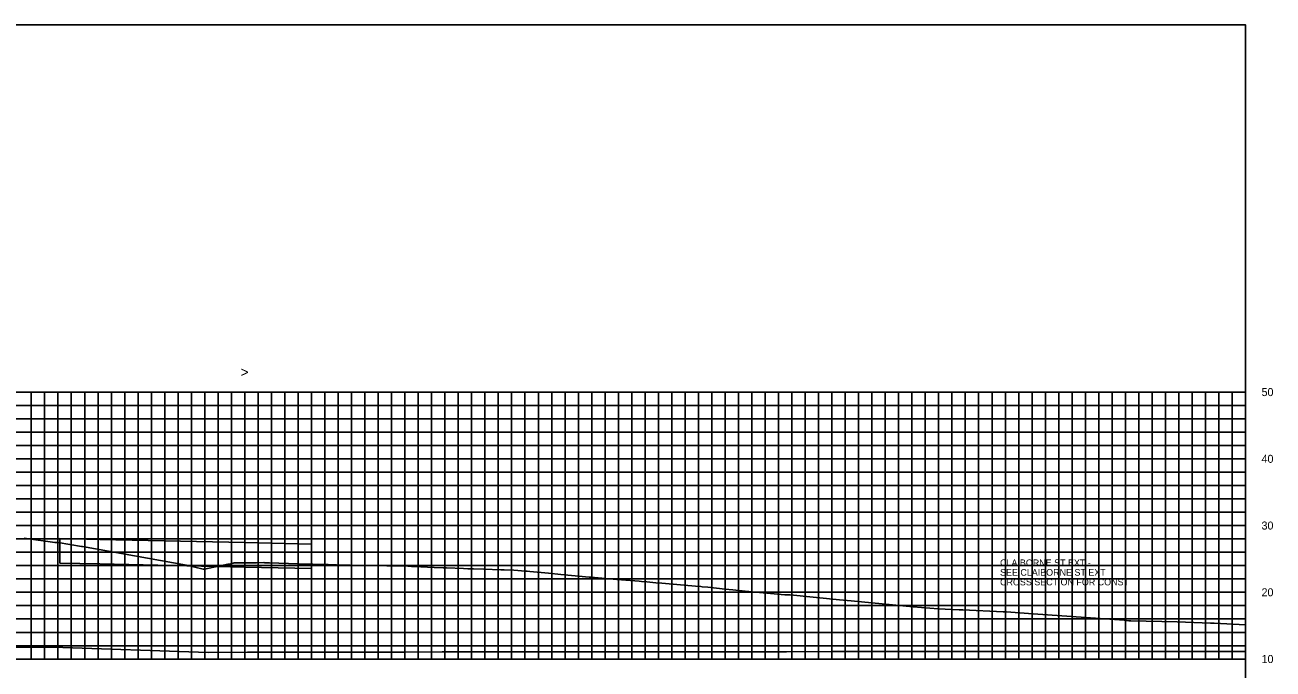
# Model space of a CAD drawing. Extents: x 1797305 to 1804485, y 245831 to 250849.
# Drawn here: x 1802938.1 to 1803125.1, y 250172.9 to 250269.4 of the extents above; entities that cross this region are included whole.
import ezdxf

# ---------------------------------------------------------------- set-up
doc = ezdxf.new("R2010")
doc.units = 0
for name, color, linetype in [('29', 7, 'Continuous'), ('60', 7, 'Continuous'), ('CL-CNST', 7, 'Continuous'), ('Level 31', 7, 'Continuous'), ('LIMT-CSLINE', 7, 'Continuous'), ('M-ROADS', 7, 'Continuous'), ('SURVEY - DRAINAGE - Area Shapes', 7, 'Continuous')]:
    doc.layers.add(name, color=color, linetype=linetype)

msp = doc.modelspace()

# ---------------------------------------------------------------- linework, layer by layer
msp.add_lwpolyline([(1802821, 250079.43), (1803121, 250079.43), (1803121, 250269.43), (1802821, 250269.43)], close=True)
at = {"layer": '29'}
for p, q in [((1802821, 250214.43), (1803121, 250214.43)), ((1802939, 250174.43), (1802939, 250214.43)), ((1802941, 250174.43), (1802941, 250214.43)), ((1802943, 250174.43), (1802943, 250214.43)), ((1802945, 250174.43), (1802945, 250214.43)), ((1802947, 250174.43), (1802947, 250214.43)), ((1802949, 250174.43), (1802949, 250214.43)), ((1802951, 250174.43), (1802951, 250214.43)), ((1802953, 250174.43), (1802953, 250214.43)), ((1802955, 250174.43), (1802955, 250214.43)), ((1802957, 250174.43), (1802957, 250214.43)), ((1802959, 250174.43), (1802959, 250214.43)), ((1802961, 250174.43), (1802961, 250214.43)), ((1802963, 250174.43), (1802963, 250214.43)), ((1802965, 250174.43), (1802965, 250214.43)), ((1802967, 250174.43), (1802967, 250214.43)), ((1802969, 250174.43), (1802969, 250214.43)), ((1802971, 250174.43), (1802971, 250214.43)), ((1802973, 250174.43), (1802973, 250214.43)), ((1802975, 250174.43), (1802975, 250214.43)), ((1802977, 250174.43), (1802977, 250214.43)), ((1802979, 250174.43), (1802979, 250214.43)), ((1802981, 250174.43), (1802981, 250214.43)), ((1802983, 250174.43), (1802983, 250214.43)), ((1802985, 250174.43), (1802985, 250214.43)), ((1802987, 250174.43), (1802987, 250214.43)), ((1802989, 250174.43), (1802989, 250214.43)), ((1802991, 250174.43), (1802991, 250214.43)), ((1802993, 250174.43), (1802993, 250214.43)), ((1802995, 250174.43), (1802995, 250214.43)), ((1802997, 250174.43), (1802997, 250214.43)), ((1802999, 250174.43), (1802999, 250214.43)), ((1803001, 250174.43), (1803001, 250214.43)), ((1803003, 250174.43), (1803003, 250214.43)), ((1803005, 250174.43), (1803005, 250214.43)), ((1803007, 250174.43), (1803007, 250214.43)), ((1803009, 250174.43), (1803009, 250214.43)), ((1803011, 250174.43), (1803011, 250214.43)), ((1803013, 250174.43), (1803013, 250214.43)), ((1803015, 250174.43), (1803015, 250214.43)), ((1803017, 250174.43), (1803017, 250214.43)), ((1803019, 250174.43), (1803019, 250214.43)), ((1803021, 250174.43), (1803021, 250214.43)), ((1803023, 250174.43), (1803023, 250214.43)), ((1803025, 250174.43), (1803025, 250214.43)), ((1803027, 250174.43), (1803027, 250214.43)), ((1803029, 250174.43), (1803029, 250214.43)), ((1803031, 250174.43), (1803031, 250214.43)), ((1803033, 250174.43), (1803033, 250214.43)), ((1803035, 250174.43), (1803035, 250214.43)), ((1803037, 250174.43), (1803037, 250214.43)), ((1803039, 250174.43), (1803039, 250214.43)), ((1803041, 250174.43), (1803041, 250214.43)), ((1803043, 250174.43), (1803043, 250214.43)), ((1803045, 250174.43), (1803045, 250214.43)), ((1803047, 250174.43), (1803047, 250214.43)), ((1803049, 250174.43), (1803049, 250214.43)), ((1803051, 250174.43), (1803051, 250214.43)), ((1803053, 250174.43), (1803053, 250214.43)), ((1803055, 250174.43), (1803055, 250214.43)), ((1803057, 250174.43), (1803057, 250214.43)), ((1803059, 250174.43), (1803059, 250214.43)), ((1803061, 250174.43), (1803061, 250214.43)), ((1803063, 250174.43), (1803063, 250214.43)), ((1803065, 250174.43), (1803065, 250214.43)), ((1803067, 250174.43), (1803067, 250214.43)), ((1803069, 250174.43), (1803069, 250214.43)), ((1803071, 250174.43), (1803071, 250214.43)), ((1803073, 250174.43), (1803073, 250214.43)), ((1803075, 250174.43), (1803075, 250214.43)), ((1803077, 250174.43), (1803077, 250214.43)), ((1803079, 250174.43), (1803079, 250214.43)), ((1803081, 250174.43), (1803081, 250214.43)), ((1803083, 250174.43), (1803083, 250214.43)), ((1803085, 250174.43), (1803085, 250214.43)), ((1803087, 250174.43), (1803087, 250214.43)), ((1803089, 250174.43), (1803089, 250214.43)), ((1803091, 250174.43), (1803091, 250214.43)), ((1803093, 250174.43), (1803093, 250214.43)), ((1803095, 250174.43), (1803095, 250214.43)), ((1803097, 250174.43), (1803097, 250214.43)), ((1803099, 250174.43), (1803099, 250214.43)), ((1803101, 250174.43), (1803101, 250214.43)), ((1803103, 250174.43), (1803103, 250214.43)), ((1803105, 250174.43), (1803105, 250214.43)), ((1803107, 250174.43), (1803107, 250214.43)), ((1803109, 250174.43), (1803109, 250214.43)), ((1803111, 250174.43), (1803111, 250214.43)), ((1803113, 250174.43), (1803113, 250214.43)), ((1803115, 250174.43), (1803115, 250214.43)), ((1803117, 250174.43), (1803117, 250214.43)), ((1803119, 250174.43), (1803119, 250214.43)), ((1803121, 250174.43), (1803121, 250214.43)), ((1802821, 250212.43), (1803121, 250212.43)), ((1802821, 250210.43), (1803121, 250210.43)), ((1802821, 250208.43), (1803121, 250208.43)), ((1802821, 250206.43), (1803121, 250206.43)), ((1802821, 250204.43), (1803121, 250204.43)), ((1802821, 250202.43), (1803121, 250202.43)), ((1802821, 250200.43), (1803121, 250200.43)), ((1802821, 250198.43), (1803121, 250198.43)), ((1802821, 250196.43), (1803121, 250196.43)), ((1802821, 250194.43), (1803121, 250194.43)), ((1802821, 250192.43), (1803121, 250192.43)), ((1802821, 250190.43), (1803121, 250190.43)), ((1802821, 250188.43), (1803121, 250188.43)), ((1802821, 250186.43), (1803121, 250186.43)), ((1802821, 250184.43), (1803121, 250184.43)), ((1802821, 250182.43), (1803121, 250182.43)), ((1802821, 250180.43), (1803121, 250180.43)), ((1802821, 250178.43), (1803121, 250178.43)), ((1802821, 250176.43), (1803121, 250176.43)), ((1802821, 250174.43), (1803121, 250174.43))]:
    msp.add_line(p, q, dxfattribs=at)
at = {"layer": 'CL-CNST'}
for points in [[(1802943.29, 250192.49), (1802949.29, 250192.36), (1802971, 250191.88), (1802981, 250191.66)], [(1802821, 250176.09), (1802825.63, 250176.01), (1802836.51, 250176.07), (1802854.79, 250176.25), (1802871.5, 250176.14), (1802883.94, 250176.21), (1802900.36, 250176.47), (1802913.1, 250176.53), (1802929.15, 250176.11), (1802942.26, 250176.19), (1802965.49, 250175.42), (1802971.42, 250175.46), (1802994.91, 250175.46), (1803000.58, 250175.49), (1803023.88, 250175.49), (1803029.74, 250175.52), (1803052.2, 250175.53), (1803058.9, 250175.54), (1803066.05, 250175.54), (1803088.05, 250175.56), (1803096.69, 250175.54), (1803117.21, 250175.56), (1803121, 250175.54)]]:
    msp.add_lwpolyline(points, dxfattribs=at)
at = {"layer": 'Level 31'}
for p, q in [((1803121, 250174.43), (1803121, 250214.43)), ((1803121.06, 250214.43), (1803121, 250214.43)), ((1803121.06, 250204.43), (1803121, 250204.43)), ((1803121.06, 250194.43), (1803121, 250194.43)), ((1803121.06, 250184.43), (1803121, 250184.43)), ((1802821, 250174.43), (1803121, 250174.43)), ((1802941, 250174.37), (1802941, 250174.43)), ((1802951, 250174.37), (1802951, 250174.43)), ((1802961, 250174.37), (1802961, 250174.43)), ((1802971, 250174.37), (1802971, 250174.43)), ((1802981, 250174.37), (1802981, 250174.43)), ((1802991, 250174.37), (1802991, 250174.43)), ((1803001, 250174.37), (1803001, 250174.43)), ((1803011, 250174.37), (1803011, 250174.43)), ((1803021, 250174.37), (1803021, 250174.43)), ((1803031, 250174.37), (1803031, 250174.43)), ((1803041, 250174.37), (1803041, 250174.43)), ((1803051, 250174.37), (1803051, 250174.43)), ((1803061, 250174.37), (1803061, 250174.43)), ((1803071, 250174.37), (1803071, 250174.43)), ((1803081, 250174.37), (1803081, 250174.43)), ((1803091, 250174.37), (1803091, 250174.43)), ((1803101, 250174.37), (1803101, 250174.43)), ((1803111, 250174.37), (1803111, 250174.43)), ((1803121, 250174.37), (1803121, 250174.43)), ((1803121.06, 250174.43), (1803121, 250174.43))]:
    msp.add_line(p, q, dxfattribs=at)
at = {"layer": 'M-ROADS'}
msp.add_lwpolyline([(1802937.93, 250192.53), (1802938.27, 250192.48), (1802942.54, 250191.9), (1802942.66, 250191.9), (1802943.04, 250191.9), (1802946.54, 250191.27), (1802946.69, 250191.28), (1802962.26, 250188.51), (1802964.76, 250187.91), (1802964.96, 250187.91), (1802968.48, 250188.62), (1802968.88, 250188.71), (1802968.93, 250188.71), (1802969.43, 250188.82), (1802969.84, 250188.82), (1802969.93, 250188.82), (1802972.07, 250188.84), (1802972.78, 250188.85), (1802973.86, 250188.87), (1802973.89, 250188.87), (1802973.91, 250188.87), (1802973.95, 250188.86), (1802974.12, 250188.86), (1802974.72, 250188.83), (1802978.93, 250188.7), (1802983.52, 250188.57), (1802986, 250188.5), (1802986.78, 250188.48), (1802988.36, 250188.43), (1802990.24, 250188.42), (1802990.31, 250188.42), (1802992.27, 250188.4), (1802992.9, 250188.39), (1802993.21, 250188.39), (1802993.4, 250188.39), (1802993.65, 250188.39), (1802993.74, 250188.39), (1802993.81, 250188.39), (1802993.86, 250188.39), (1802993.91, 250188.39), (1802994.11, 250188.38), (1802994.19, 250188.39), (1802994.31, 250188.38), (1802994.32, 250188.38), (1802995.44, 250188.33), (1802995.62, 250188.32), (1802995.99, 250188.31), (1802996.33, 250188.31), (1802997.37, 250188.25), (1802999.4, 250188.14), (1803000.76, 250188.09), (1803001.22, 250188.08), (1803003.8, 250187.99), (1803004.43, 250187.96), (1803005.29, 250187.94), (1803006.83, 250187.89), (1803009.36, 250187.81), (1803009.86, 250187.79), (1803011.32, 250187.75), (1803013.1, 250187.6), (1803013.33, 250187.58), (1803013.72, 250187.54), (1803013.72, 250187.54), (1803016.53, 250187.29), (1803018.36, 250187.12), (1803019.95, 250186.97), (1803022.61, 250186.72), (1803023.08, 250186.68), (1803023.38, 250186.65), (1803023.41, 250186.65), (1803024.5, 250186.55), (1803026.76, 250186.36), (1803027.46, 250186.3), (1803030.13, 250186.08), (1803030.48, 250186.05), (1803031.24, 250185.99), (1803032.63, 250185.87), (1803033.49, 250185.8), (1803036.3, 250185.56), (1803036.85, 250185.52), (1803038.56, 250185.37), (1803039.34, 250185.29), (1803039.55, 250185.27), (1803040.4, 250185.18), (1803043.02, 250184.92), (1803044.14, 250184.8), (1803046.02, 250184.6), (1803051.96, 250184.04), (1803052.34, 250184.04), (1803052.73, 250184.03), (1803060.14, 250183.31), (1803061.88, 250183.14), (1803071.17, 250182.25), (1803074.93, 250181.94), (1803078.08, 250181.81), (1803078.65, 250181.79), (1803084.68, 250181.48), (1803085.09, 250181.48), (1803085.18, 250181.48), (1803088.46, 250181.26), (1803089.15, 250181.21), (1803102.83, 250180.26), (1803103.49, 250180.16), (1803103.83, 250180.16), (1803110.77, 250179.98), (1803115.77, 250179.81), (1803116.06, 250179.81), (1803116.28, 250179.81), (1803121, 250179.53)], dxfattribs=at)
at = {"layer": 'SURVEY - DRAINAGE - Area Shapes'}
msp.add_lwpolyline([(1802981, 250187.98), (1802981, 250191.66), (1802971, 250191.88), (1802949.29, 250192.36), (1802943.29, 250192.49), (1802943.29, 250188.81), (1802949.29, 250188.68), (1802971, 250188.2)], close=True, dxfattribs=at)

# ---------------------------------------------------------------- texts
at = {"layer": '60'}
for s, p in [('50', (1803123.4, 250213.83)), ('40', (1803123.4, 250203.83)), ('30', (1803123.4, 250193.83)), ('20', (1803123.4, 250183.83)), ('10', (1803123.4, 250173.83))]:
    msp.add_text(s, height=1.2, dxfattribs=at).set_placement(p)
at = {"layer": 'Level 31'}
msp.add_text('>', height=1.5, dxfattribs=at).set_placement((1802970.39, 250216.68))
at = {"layer": 'LIMT-CSLINE'}
for s, p in [('CLAIBORNE ST EXT -', (1803084.21, 250188.35)), ('SEE CLAIBORNE ST EXT', (1803084.21, 250186.91)), ('CROSS SECTION FOR CONST ', (1803084.21, 250185.47))]:
    msp.add_text(s, height=1, dxfattribs=at).set_placement(p)

doc.saveas('drawing.dxf')
